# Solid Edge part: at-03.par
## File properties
Author: nakano
Template: iso metric part.par
Last saved by: nakano
Revision: 4
Application: Solid Edge
Density: 2953.01448920965 kg/m^3
Accuracy: 0.990
Username: nakano
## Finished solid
Body 1: solid body, 8 faces, 12 edges, 0 vertices.
  Faces by surface: cylinder 6, plane 2
  Edges by curve: intersection 8, circle 4
Bounding box of the edges (mm): 12.700 x 12.700 x 114.300, from (-6.35, -6.35, 0) to (6.35, 6.35, 114.3).
Cylindrical faces by radius (mm): R2 x4, R5.461 x1, R6.35 x1
Planar faces by outward normal: +z 1, -z 1
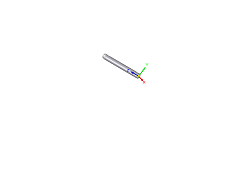
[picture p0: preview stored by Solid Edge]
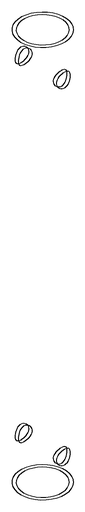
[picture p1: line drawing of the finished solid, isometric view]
